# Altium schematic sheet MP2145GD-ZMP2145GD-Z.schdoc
size 127 x 101 mm
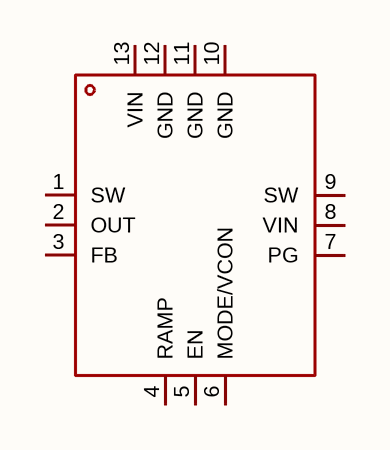
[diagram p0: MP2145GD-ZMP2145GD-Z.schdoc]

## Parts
U?  mp2145gd-z  [QFN-12_L3.0-W2.0_MP2145GD-Z]  (value not drawn)

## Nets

Not connected (* = marked no-connect by the designer): U? 1(SW) 2(OUT) 3(FB) 4(RAMP) 5(EN) 6(MODE/VCON) 7(PG) 8(VIN) 9(SW) 10(GND) 11(GND) 12(GND) 13(VIN)

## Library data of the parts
U? = mp2145gd-z: 功能类型:降压型;输出类型:可调;工作电压:2.8V~5.5V;输出电压:600mV~5.5V;输出电流:6A;; Manufacturer: MPS(芯源); AddInBom: yes; ModelId: 99dbf81482c0458d9d71299d94261e77; ModelTransform: 118.11,78.74,0,0,0,0,0,0,0; Function: 降压型; Output Type: 可调; Output Current: 6A; Frequency - Switching: 1.2MHz; Synchronous Rectifier: 是; Number of Outputs: 1; Topology: 降压式; Quiescent Current: 40uA; Switch tube (built-in/external): 内置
